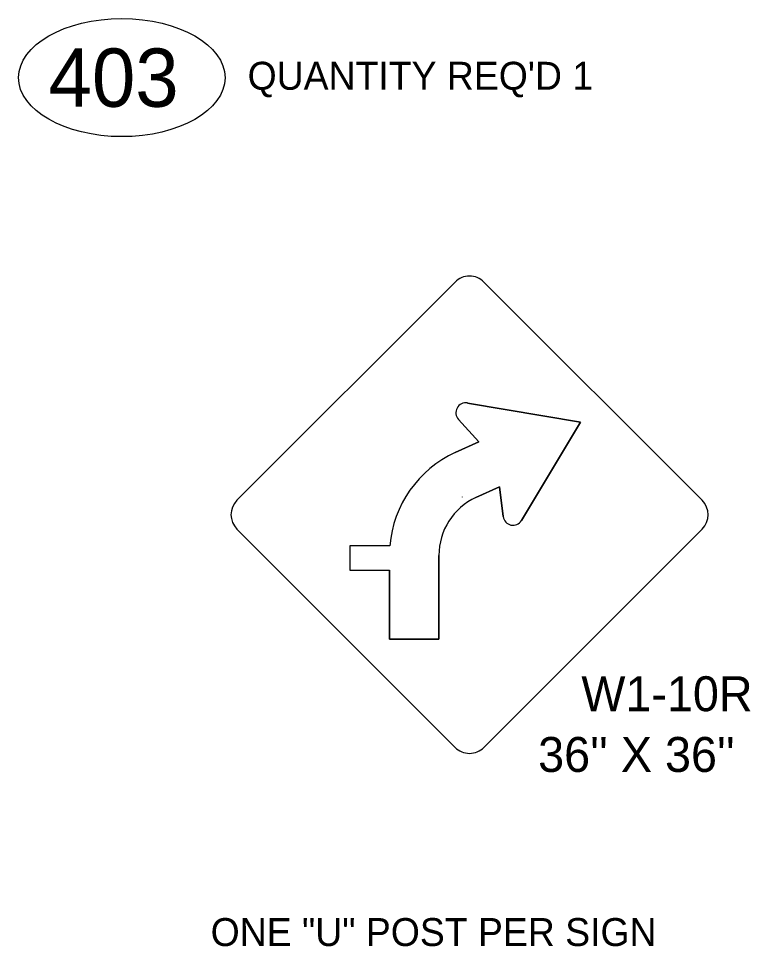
# Model space of a CAD drawing. Extents: x 1977705 to 1981198, y 827296 to 829291.
# Drawn here: x 1978508.4 to 1978665.6, y 828037.1 to 828236.2 of the extents above; entities that cross this region are included whole.
import ezdxf

# ---------------------------------------------------------------- set-up
doc = ezdxf.new("R2010")
doc.units = 0
doc.layers.add('Default', color=7, linetype='Continuous')
doc.layers.add('Level 11', color=7, linetype='Continuous')

msp = doc.modelspace()

# ---------------------------------------------------------------- linework, layer by layer
at = {"layer": 'Default'}
for p, q in [((1978604.83, 828153.73), (1978604.83, 828153.72)), ((1978604.83, 828153.72), (1978604.83, 828153.73)), ((1978604.83, 828153.72), (1978629.09, 828149.63)), ((1978629.09, 828149.63), (1978604.83, 828153.72)), ((1978629.09, 828149.63), (1978616.44, 828128.51)), ((1978616.44, 828128.51), (1978629.09, 828149.63)), ((1978611.75, 828135.77), (1978606.67, 828133.45)), ((1978606.67, 828133.45), (1978611.75, 828135.77)), ((1978612.51, 828129.34), (1978611.75, 828135.77)), ((1978611.75, 828135.77), (1978612.51, 828129.34)), ((1978603.77, 828133.53), (1978603.75, 828133.56)), ((1978608.38, 828079.81), (1978655.22, 828126.65)), ((1978598.71, 828121.02), (1978598.72, 828103.04)), ((1978598.72, 828103.04), (1978598.71, 828121.02)), ((1978588.08, 828113.71), (1978588.08, 828117.86)), ((1978588.08, 828117.86), (1978588.08, 828113.71)), ((1978588.09, 828103.04), (1978588.08, 828113.71)), ((1978588.08, 828113.71), (1978588.09, 828103.04)), ((1978598.72, 828103.04), (1978588.09, 828103.04)), ((1978588.09, 828103.04), (1978598.72, 828103.04))]:
    msp.add_line(p, q, dxfattribs=at)
for points in [[(1978602.19, 828179.69), (1978555.34, 828132.84)], [(1978655.22, 828132.84), (1978608.38, 828179.69)], [(1978602.22, 828143.11), (1978607.3, 828145.43), (1978602.91, 828150.2)], [(1978602.91, 828150.2), (1978607.3, 828145.43), (1978602.22, 828143.11)], [(1978555.34, 828126.65), (1978602.19, 828079.81)], [(1978588.17, 828123.1), (1978579.56, 828123.1), (1978579.56, 828117.86), (1978588.08, 828117.86)], [(1978588.17, 828123.1), (1978579.56, 828123.1), (1978579.56, 828117.86), (1978588.08, 828117.86)]]:
    msp.add_lwpolyline(points, dxfattribs=at)
for centre, radius, start, end in [((1978605.28, 828176.59), 4.38, 89.9935, 135), ((1978605.28, 828176.59), 4.38, 44.987, 89.9935), ((1978604.48, 828151.64), 2.12, 80.3995, 222.5215), ((1978604.48, 828151.64), 2.12, 80.3995, 222.5215), ((1978612.39, 828121.02), 24.31, 114.7238, 175.104), ((1978612.39, 828121.02), 24.31, 114.7238, 175.104), ((1978558.44, 828129.75), 4.38, 135, 225), ((1978612.39, 828121.02), 13.68, 114.7238, 180.0308), ((1978612.39, 828121.02), 13.68, 114.7238, 180.0308), ((1978652.13, 828129.75), 4.38, 315, 45), ((1978614.62, 828129.6), 2.12, 186.9194, 329.0479), ((1978614.62, 828129.6), 2.12, 186.9194, 329.0479), ((1978605.28, 828082.9), 4.38, 225, 270), ((1978605.28, 828082.9), 4.38, 270, 315)]:
    msp.add_arc(centre, radius, start, end, dxfattribs=at)
at = {"layer": 'Level 11'}
msp.add_ellipse((1978530.61, 828223.57), major_axis=(-22.17, 0.01), ratio=0.571429, dxfattribs=at)

# ---------------------------------------------------------------- texts
at = {"layer": 'Default'}
for s, height, p in [("QUANTITY REQ'D 1", 6, (1978557.63, 828220.97)), ('W1-10R', 7.5, (1978629.3, 828087.57)), ("36'' X 36''", 7.5002, (1978620.02, 828074.54)), ('ONE "U" POST PER SIGN', 6, (1978549.69, 828037.17))]:
    msp.add_text(s, height=height, dxfattribs=at).set_placement(p)
at = {"layer": 'Level 11'}
msp.add_text('403', height=12.516, rotation=359.9659, dxfattribs=at).set_placement((1978514.89, 828217.32))

doc.saveas('drawing.dxf')
